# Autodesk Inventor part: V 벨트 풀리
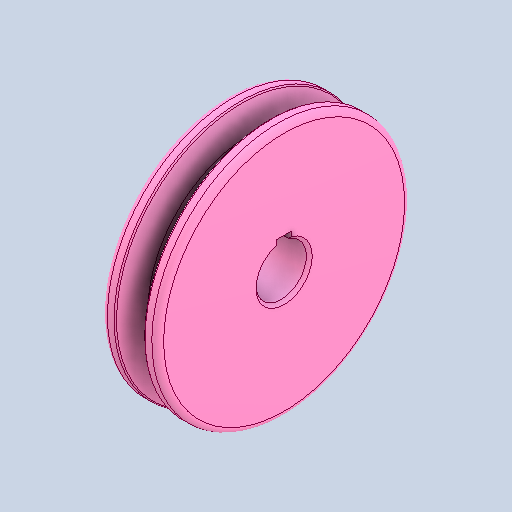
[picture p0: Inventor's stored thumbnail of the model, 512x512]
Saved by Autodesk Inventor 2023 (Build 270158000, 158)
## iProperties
Created: 2025-03
Part Number: V 벨트 풀리
Material: 알루미늄 6061
Document SubType Name: Modeling
Designer: Admin
Density: 2.71 g/cm^3
Appearance: 기본값
Author: jhkim
Sending System: Autodesk Inventor 2025
Preprocessor: ST-DEVELOPER v20
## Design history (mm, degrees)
feature "솔리드1"
node "솔리드2"
